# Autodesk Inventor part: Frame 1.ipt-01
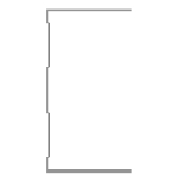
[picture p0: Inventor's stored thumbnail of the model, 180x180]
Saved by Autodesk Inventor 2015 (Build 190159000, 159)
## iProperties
Created: 2015-04
Part Number: Frame 1.ipt-01
Material: Aluminum 6061
Description: Kévin Novo
Document SubType Name: Modeling
Standard: Kevin
Designer: suporte
Standards Organization: Kevin
Language: en-US
Size Designation: (Unnamed 1)
Categories: <MemberInstance><Categories><Category DisplayName="Structural Shapes" InternalName="089c4875-fa83-4c05-b084-43b9cc11f5ed" Mnemonic="GRDR"><CategoryParameter Dis
Density: 2.7 g/cm^3
Appearance: Aluminum - Flat
IsCustomPart: 1
_CCFamilyMember: 1
_CCFamilyDisplayName: Kévin - Kévin Novo
_FrameMemberDoc: Frame Member File
_Version: 15.0.0
_GetPNFromCC: 1
G_L: 1275,000 mm
G_W: 50,000 mm
G_H: 75,000 mm
+D87C0F32-8461-4F19-A6E5-F7FFCE7659D3+CUTDETAIL1: Cut
+ACB6C8C3-AA69-4D4C-B27A-0D4BF8BA8BC6+CUTDETAIL2: Cut
Author: suporte
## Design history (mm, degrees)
node "Start Plane"
node "End Plane"
sketch "Sketch"
  geometry: L1 (24.7, 37.5)-(24.7, 36.9); L2 (24.7, 36.9)-(-24.7, 36.9); L3 (-24.7, -36.9)-(24.7, -36.9); L4 (24.7, -36.9)-(24.7, -37.5); L5 (24.7, -37.5)-(-25.3, -37.5); L6 (-25.3, 37.5)-(24.7, 37.5); L7 (-24.7, 36.9)-(-24.7, 31.9); L8 (-24.7, 31.9)-(-23.3, 30.5); L9 (-23.3, 30.5)-(-23.3, 10.934); L10 (-23.3, 10.934)-(-24.7, 9.534); L11 (-24.7, 9.534)-(-24.7, -9.534); L12 (-24.7, -9.534)-(-23.3, -10.934); L13 (-23.3, -10.934)-(-23.3, -30.5); L14 (-23.3, -30.5)-(-24.7, -31.9); L15 (-24.7, -31.9)-(-24.7, -36.9); L16 (-25.3, -37.5)-(-25.3, -31.651); L17 (-25.3, -31.651)-(-23.9, -30.251); L18 (-23.9, -30.251)-(-23.9, -11.183); L19 (-23.9, -11.183)-(-25.3, -9.783); L20 (-25.3, -9.783)-(-25.3, 9.783); L21 (-25.3, 9.783)-(-23.9, 11.183); L22 (-23.9, 11.183)-(-23.9, 30.251); L23 (-23.9, 30.251)-(-25.3, 31.651); L24 (-25.3, 31.651)-(-25.3, 37.5); L25 (-25.3, 0)-(30.37, 0); 3 further points
  constraints: 50 end point, 10 point on line, 9 parallel, 5 perpendicular, 4 equal length, 3 midpoint, 3 vertical, 2 vertical alignment, 1 collinear, 1 horizontal, 1 horizontal alignment
  dimensions: "d3" = 0.6 distance of L1.start L1.end (= d6); "d5" = 75 distance between parallel lines of L5 L6; "d6" = 0.6 distance between parallel lines of L24 L7 (= d8); "d7" = 0.6 distance between parallel lines of L8 L23 (= d8); "d8" = 0.6 distance between parallel lines of L22 L9 (= d12); "Espessura" = 0.6 distance between parallel lines of L17 L14; "d10" = 0.6 distance between parallel lines of L13 L18 (= Espessura); "d11" = 0.6 distance between parallel lines of L12 L19 (= Espessura); "d12" = 0.6 distance between parallel lines of L21 L10 (= d11); "d13" = 5 distance of L2.end L7.end; "d15" = 135 deg angle of L9 L8; "d16" = 2 distance between parallel lines of L24 L9; "d17" = 50 distance of L6.start L1.start
extrude "Body" join sketch "Sketch" stored distance "d24" = 0.13; taper "d25" = 0 deg
node "Driven Length"
  sketch "Sketch10"
    geometry: L1 (0, 0)-(10, 0) reference
    constraints: 2 end point, 1 horizontal
  workplane "Work Plane7"
  sketch "Sketch11"
    geometry: L1 (-2, 12.5)-(12, 12.5) reference; L2 (-2, 1287.5)-(12, 1287.5) reference
    dimensions: "d27" = 1275 distance between parallel lines of L1 L2 (derived)
workplane "Work Plane8"
split "Split1"
workplane "Work Plane9"
split "Split2"
body "Solid1"
other parameters: "G_OFFSET_START" = -12.5 [user parameter; used in 1 equation term], "G_OFFSET_END" = 87.5 [user parameter; used in 1 equation term], "d22" = 12.5 (= -G_OFFSET_START), "d23" = 1287.5 (= tamanho + G_OFFSET_END), "G_L" = 1275 (= d27) [user parameter], "d34" = 90 deg
